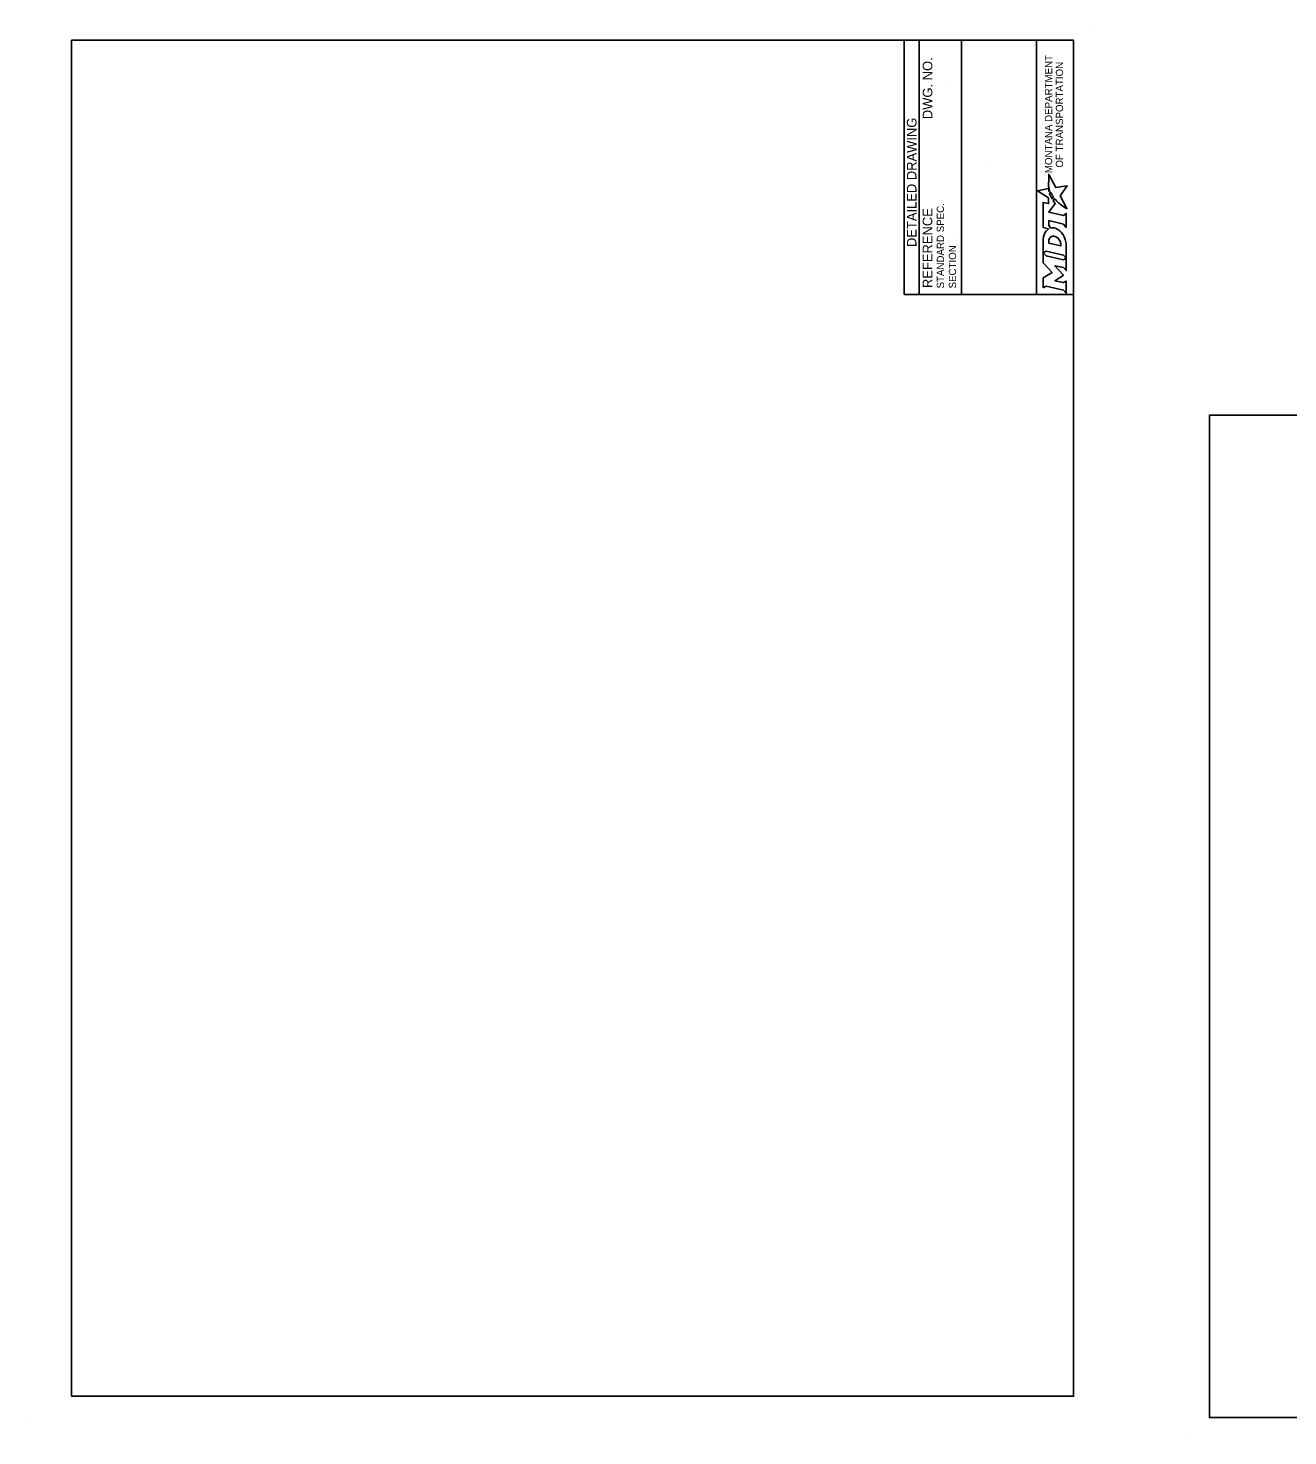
# Model space of a CAD drawing. Extents: x 49991.4 to 50021, y 49987.6 to 50011.4.
# Drawn here: x 49999.98 to 50010.39, y 49999.74 to 50011.36 of the extents above; entities that cross this region are included whole.
import ezdxf

# ---------------------------------------------------------------- set-up
doc = ezdxf.new("R2010")
doc.units = 0
doc.layers.add('Level 1', color=7, linetype='Continuous')
doc.layers.add('Level 3', color=7, linetype='Continuous')

msp = doc.modelspace()

# ---------------------------------------------------------------- linework, layer by layer
at = {"layer": 'Level 1'}
for p, q in [((50008.765, 50011.363), (50008.765, 50011.363)), ((49999.977, 49999.862), (49999.977, 49999.862)), ((50009.537, 49999.736), (50009.537, 49999.736))]:
    msp.add_line(p, q, dxfattribs=at)
for points in [[(50008.615, 50011.263), (50000.336, 50011.263), (50000.336, 50000.062), (50008.615, 50000.062)], [(50020.938, 50008.165), (50009.737, 50008.165), (50009.737, 49999.886), (50020.938, 49999.886)]]:
    msp.add_lwpolyline(points, close=True, dxfattribs=at)
at = {"layer": 'Level 3'}
for p, q in [((50007.215, 50011.263), (50007.215, 50009.163)), ((50007.34, 50011.263), (50007.34, 50009.163)), ((50007.69, 50011.263), (50007.69, 50009.163)), ((50008.308, 50011.263), (50008.308, 50009.163)), ((50007.555, 50010.899), (50007.555, 50010.899)), ((50007.939, 50010.213), (50007.939, 50010.213)), ((50007.614, 50009.657), (50007.614, 50009.657)), ((50007.215, 50009.163), (50008.615, 50009.163))]:
    msp.add_line(p, q, dxfattribs=at)
for points in [[(50008.514, 50009.9), (50008.538, 50009.885), (50008.546, 50009.88), (50008.554, 50009.875), (50008.559, 50009.872), (50008.505, 50009.978), (50008.561, 50010.061), (50008.468, 50010.048), (50008.409, 50010.155), (50008.409, 50010.106), (50008.408, 50010.076), (50008.408, 50010.055), (50008.409, 50010.048), (50008.411, 50010.043), (50008.413, 50010.035), (50008.417, 50010.025)], [(50008.417, 50010.025), (50008.411, 50010.014), (50008.409, 50010.026), (50008.407, 50010.038), (50008.316, 50010.02), (50008.408, 50009.961), (50008.408, 50009.914), (50008.364, 50009.924), (50008.364, 50009.715), (50008.407, 50009.705), (50008.398, 50009.699)], [(50008.445, 50009.974), (50008.446, 50009.972), (50008.437, 50009.954), (50008.431, 50009.964), (50008.429, 50009.968), (50008.425, 50009.977), (50008.422, 50009.982), (50008.419, 50009.99), (50008.416, 50009.998), (50008.424, 50010.009), (50008.426, 50010.005), (50008.428, 50010.001), (50008.431, 50009.997), (50008.434, 50009.992), (50008.435, 50009.99), (50008.436, 50009.987), (50008.438, 50009.985), (50008.439, 50009.982), (50008.441, 50009.98), (50008.443, 50009.977), (50008.445, 50009.974)], [(50008.423, 50009.711), (50008.41, 50009.736), (50008.41, 50009.773), (50008.531, 50009.744), (50008.553, 50009.717), (50008.553, 50009.833), (50008.531, 50009.816), (50008.41, 50009.844), (50008.462, 50009.915), (50008.447, 50009.937), (50008.458, 50009.956)], [(50008.498, 50009.914), (50008.498, 50009.914)], [(50008.451, 50009.644), (50008.459, 50009.643), (50008.468, 50009.64), (50008.476, 50009.635), (50008.484, 50009.63), (50008.491, 50009.623), (50008.497, 50009.615), (50008.502, 50009.607), (50008.506, 50009.598), (50008.508, 50009.589), (50008.509, 50009.58), (50008.509, 50009.564), (50008.409, 50009.587), (50008.409, 50009.603), (50008.41, 50009.611), (50008.412, 50009.619), (50008.415, 50009.625), (50008.419, 50009.631), (50008.424, 50009.636), (50008.43, 50009.64), (50008.436, 50009.642), (50008.443, 50009.644), (50008.446, 50009.644), (50008.451, 50009.644)], [(50008.546, 50009.618), (50008.543, 50009.626), (50008.538, 50009.639), (50008.527, 50009.66)], [(50008.364, 50009.62), (50008.364, 50009.506), (50008.387, 50009.521), (50008.531, 50009.487), (50008.553, 50009.462), (50008.553, 50009.572)], [(50008.387, 50009.481), (50008.364, 50009.506), (50008.364, 50009.424), (50008.437, 50009.344), (50008.364, 50009.3), (50008.364, 50009.218)], [(50008.364, 50009.218), (50008.388, 50009.232), (50008.531, 50009.198), (50008.553, 50009.173), (50008.553, 50009.274), (50008.531, 50009.261), (50008.461, 50009.277), (50008.53, 50009.321), (50008.53, 50009.326), (50008.46, 50009.401), (50008.531, 50009.385), (50008.553, 50009.36), (50008.553, 50009.462), (50008.53, 50009.448), (50008.387, 50009.481)]]:
    msp.add_lwpolyline(points, dxfattribs=at)
for centre, radius, start, end in [((50008.443, 50009.643), 0.0709, 69.5329, 105.8582), ((50008.425, 50009.599), 0.118, 30.9103, 69.1383)]:
    msp.add_arc(centre, radius, start, end, dxfattribs=at)
for centre, major_axis, ratio, start_param, end_param in [((50008.468, 50009.945), (0.0097, -0.0112), 0.021651, 3.157348, 6.283185), ((50008.487, 50009.924), (0.0102, -0.0098), 0.016458, 3.141593, 6.279097), ((50008.506, 50009.907), (0.00806, -0.00694), 0.008222, 0, 3.137361), ((50008.412, 50009.618), (0.0037, 0.0834), 0.568097, 0.61298, 1.570796), ((50008.404, 50009.673), (0.0295, 0.0361), 0.469099, 1.225588, 1.570796), ((50008.405, 50009.573), (-0.148, 0), 0.987302, 3.139398, 3.456847)]:
    msp.add_ellipse(centre, major_axis=major_axis, ratio=ratio, start_param=start_param, end_param=end_param, dxfattribs=at)

# ---------------------------------------------------------------- texts
for s, height, p in [('DWG. NO.', 0.08, (50007.448, 50010.611)), ('MONTANA DEPARTMENT', 0.06, (50008.438, 50010.165)), ('OF TRANSPORTATION', 0.06, (50008.528, 50010.211)), ('DETAILED DRAWING', 0.0799, (50007.317, 50009.555)), ('REFERENCE', 0.08, (50007.448, 50009.216)), ('STANDARD SPEC.', 0.06, (50007.544, 50009.213)), ('SECTION', 0.06, (50007.644, 50009.213))]:
    msp.add_text(s, height=height, rotation=90, dxfattribs=at).set_placement(p)

doc.saveas('drawing.dxf')
